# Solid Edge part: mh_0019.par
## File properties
Title: stopper
Author: edge
Template: normal.par
Last saved by: edge
Revision: 36
Application: Solid Edge
Material: エラストマ
非切断部品: False
文書内容のタイプ: 0
Density: 0.001030 g/mm^3
Accuracy: 0.99
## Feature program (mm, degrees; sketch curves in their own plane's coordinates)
sketch for "unnamed Protrusion 1" plane through (0, 0, 0) normal (1, 0, 0) x-axis (0, 1, 0)
extrude "unnamed Protrusion 1" add finite 5 along -normal
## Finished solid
Body 1: solid body, 6 faces, 12 edges, 8 vertices.
  Faces by surface: plane 6
  Edges by curve: line 12
Bounding box of the edges (mm): 5.000 x 15.000 x 25.000, from (-5, -7.5, -12.5) to (0, 7.5, 12.5).
Planar faces by outward normal: +x 1, +y 1, +z 1, -x 1, -y 1, -z 1
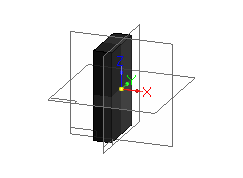
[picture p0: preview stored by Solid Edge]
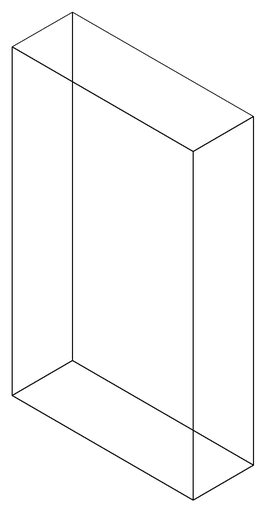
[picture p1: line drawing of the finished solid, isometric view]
